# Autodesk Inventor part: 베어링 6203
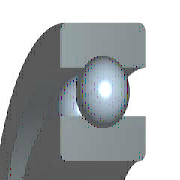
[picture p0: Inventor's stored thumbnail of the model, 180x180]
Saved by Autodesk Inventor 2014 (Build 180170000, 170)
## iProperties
IsCustomPart: 1
Created: 2015-09
Part Number: 베어링 6203
Material: 강철, 연강
Description: 깊은 그루브 볼 베어링
Document SubType Name: Modeling
Standard: KS B 2023
Standards Organization: KS
Language: ko-KR
Size Designation: 6203 - 17 x 40 x 12
Categories: <MemberInstance><Categories><Category DisplayName="샤프트 부품" InternalName="7f7aeb1f-a693-4053-b835-cee3144e0d98" Mnemonic="SHFT"><Category DisplayName="베어링" Inter
Density: 7.86 g/cm^3
Mass: 64.9809 g
Surface Area: 64.3582 cm^2
Volume: 8.26729 cm^3
Appearance: Steel
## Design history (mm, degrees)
sketch "스케치" dims "d0" = 5.98 (= -0.26 x WD + 0.26 x BD)
  geometry: L1 (3.01, 14.25)-(8.99, 14.25); L2 (6, 14.25)-(6, 11.26); L3 (6, 14.25)-(6, 17.24); L4 (3.778, 12.249)-(0, 12.249); L5 (0, 8.5)-(12, 8.5); L6 (3.778, 16.251)-(0, 16.251); L7 (0, 20)-(12, 20); L8 (12, 8.5)-(12, 12.249); L9 (8.222, 12.249)-(12, 12.249); L10 (8.222, 16.251)-(12, 16.251); L11 (12, 20)-(12, 16.251); L12 (-1.4, 0)-(8.4, 0) reference; L13 (0, -0.3)-(0, 5.3) reference
  constraints: 22 end point, 4 point on line, 2 collinear, 2 perpendicular, 2 symmetric about line, 1 midpoint, 1 parallel, 14 other
  dimensions: "d9" = 17 diameter of L5 L12 (= WD); "d11" = 40 diameter of L7 L12 (= BD); "d12" = 12 distance between parallel lines of L8 L13 (= KB); "d13" = 24.498 diameter of L9 L12 (= 0.326 x BD + 0.674 x WD)
revolve "본체" stored, may be unused: angle "d6" = 90 deg
revolve "볼" stored, may be unused: angle "d7" = 90 deg
pattern_circular "IDS_ARRAYBALL[SIMPL:T]" dims angle "d3" = 360 deg
body "Solid1"
fillet "모깎기1" dims "d1" = 0.6 (= KRS)
other parameters: "WD" = 17 [user parameter; used in 5 equation terms], "BD" = 40 [user parameter; used in 5 equation terms], "KB" = 12 [user parameter; used in 1 equation term], "KRS" = 0.6 [user parameter; used in 1 equation term], "d4" = 0, "d5" = 0, "d8" = 0, "d14" = 0, "d15" = 0, "BBA" = 0 [user parameter], "BC0" = 4750000 [user parameter], "BC" = 9560000 [user parameter], "WR" = 8.5 (= 0.5 x WD) [user parameter]
